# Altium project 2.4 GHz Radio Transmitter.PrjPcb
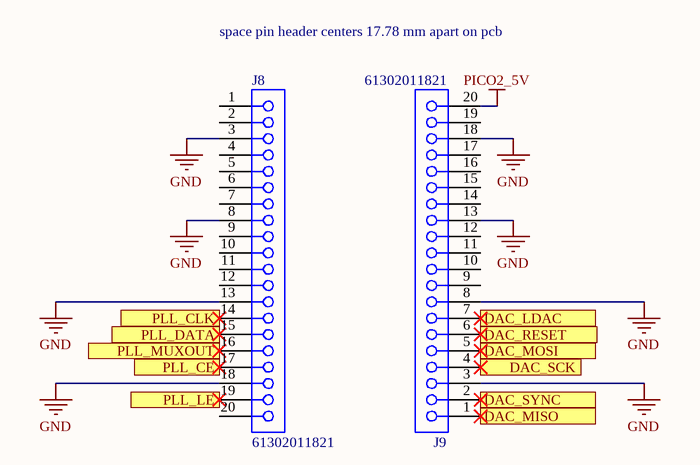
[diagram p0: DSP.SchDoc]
5 sheets, 215 parts. Net scope: flat (ports and power ports of the same name join across sheets).
Board file: 2.4 GHz Radio Transmitter.PcbDoc
Sheets:
  DSP.SchDoc
  PowerFilterLDO.SchDoc
  AnalogBaseband.SchDoc
  FrequencySynthesis.SchDoc
  RF_FrontEnd.SchDoc

## Sheet DSP.SchDoc
size A; SheetNumber: 1; SheetTotal: 5

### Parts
J8  61302011821  [61302011821]
J9  61302011821  [61302011821]

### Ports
DAC_LDAC (see AnalogBaseband[2B]), DAC_MISO (see AnalogBaseband[3A]), DAC_MOSI (see AnalogBaseband[3A]), DAC_RESET (see AnalogBaseband[2B]), DAC_SCK (see AnalogBaseband[3A]), DAC_SYNC (see AnalogBaseband[2A]), PLL_CE (see FrequencySynthesis[3B]), PLL_CLK (see FrequencySynthesis[3B]), PLL_DATA (see FrequencySynthesis[3B]), PLL_LE (see FrequencySynthesis[4B]), PLL_MUXOUT (see FrequencySynthesis[4B])

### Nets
GND: J8.3 J8.8 J8.13 J8.18 J9.3 J9.8 J9.13 J9.18
PICO2_5V: J9.20
NetJ8_14: J8.14 ; port PLL_CLK
NetJ8_15: J8.15 ; port PLL_DATA
NetJ8_16: J8.16 ; port PLL_MUXOUT
NetJ8_17: J8.17 ; port PLL_CE
NetJ8_19: J8.19 ; port PLL_LE
NetJ9_1: J9.1 ; port DAC_MISO
NetJ9_2: J9.2 ; port DAC_SYNC
NetJ9_4: J9.4 ; port DAC_SCK
NetJ9_5: J9.5 ; port DAC_MOSI
NetJ9_6: J9.6 ; port DAC_RESET
NetJ9_7: J9.7 ; port DAC_LDAC

Not connected (* = marked no-connect by the designer): J8 1 2 4 5 6 7 9 10 11 12 20; J9 9 10 11 12 14 15 16 17 19

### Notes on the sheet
- space pin header centers 17.78 mm apart on pcb

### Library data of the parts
J8 J9 = CMP-1502-01348-4: THT Vertical Socket Header WR-PHD, Pitch 2.54 mm, Single Row, 20 pins; Contact Resistance: 20mΩ; Gender: Female; Current Rating: 3A; Operating Supply Voltage: 250V

## Sheet PowerFilterLDO.SchDoc
size B; SheetNumber: 2; SheetTotal: 5
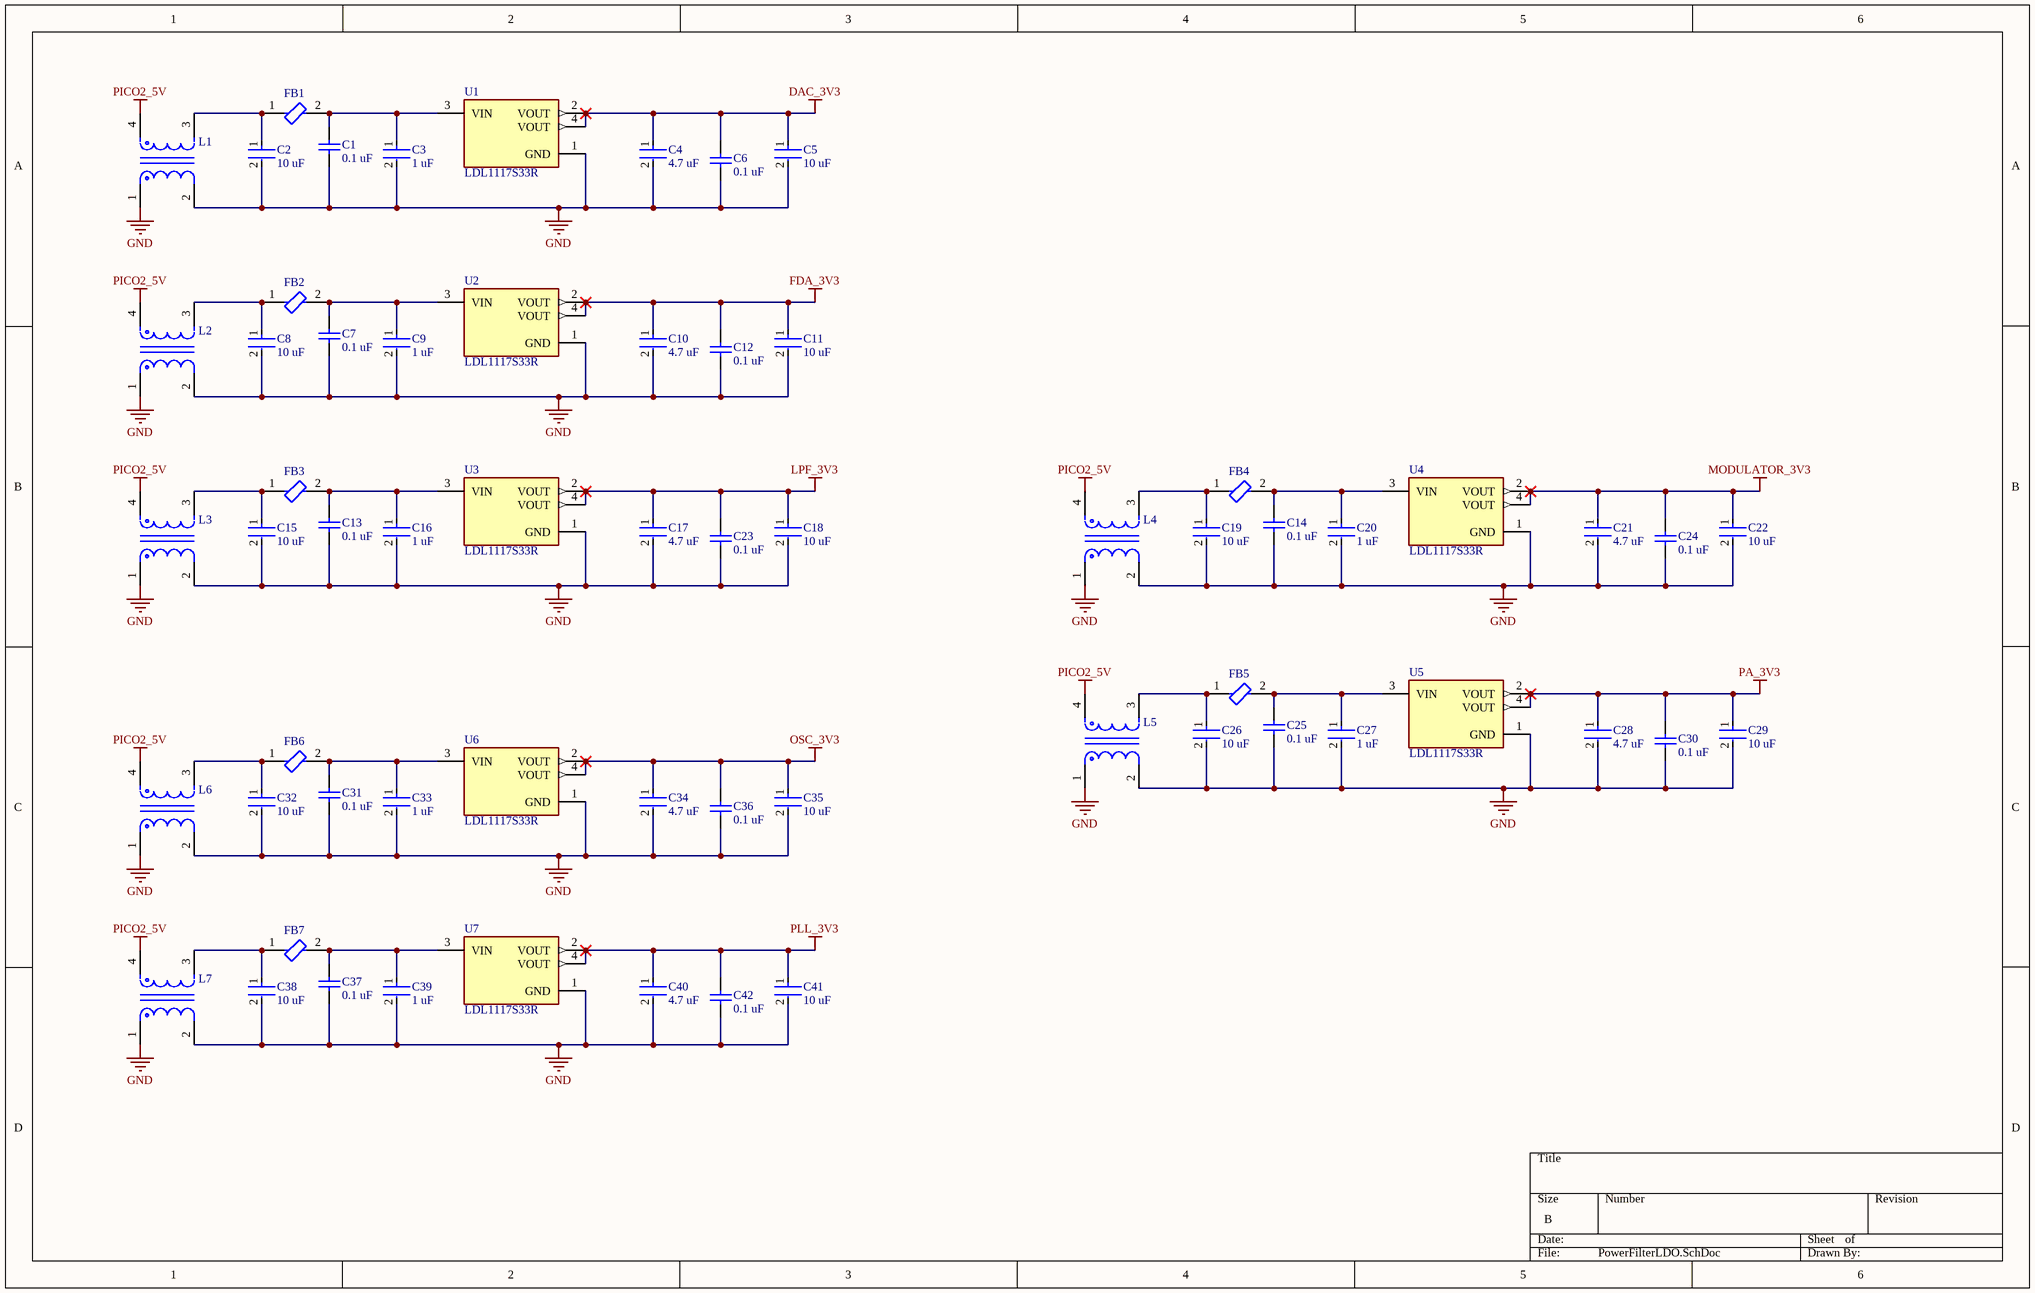
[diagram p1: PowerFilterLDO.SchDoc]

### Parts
C1  0.1 uF  [CAPC1608X95X40LL15T15]
C2  10 uF  [FP-GCM21B-0_15-IPC_A]
C3  1 uF  [FP-VJ0603Y105KXJCW1BC-MFG]
C4  4.7 uF  [FP-GCJ21B-0_3-IPC_A]
C5  10 uF  [FP-GCM21B-0_15-IPC_A]
C6  0.1 uF  [CAPC1608X95X40LL15T15]
C7  0.1 uF  [CAPC1608X95X40LL15T15]
C8  10 uF  [FP-GCM21B-0_15-IPC_A]
C9  1 uF  [FP-VJ0603Y105KXJCW1BC-MFG]
C10  4.7 uF  [FP-GCJ21B-0_3-IPC_A]
C11  10 uF  [FP-GCM21B-0_15-IPC_A]
C12  0.1 uF  [CAPC1608X95X40LL15T15]
C13  0.1 uF  [CAPC1608X95X40LL15T15]
C14  0.1 uF  [CAPC1608X95X40LL15T15]
C15  10 uF  [FP-GCM21B-0_15-IPC_A]
C16  1 uF  [FP-VJ0603Y105KXJCW1BC-MFG]
C17  4.7 uF  [FP-GCJ21B-0_3-IPC_A]
C18  10 uF  [FP-GCM21B-0_15-IPC_A]
C19  10 uF  [FP-GCM21B-0_15-IPC_A]
C20  1 uF  [FP-VJ0603Y105KXJCW1BC-MFG]
C21  4.7 uF  [FP-GCJ21B-0_3-IPC_A]
C22  10 uF  [FP-GCM21B-0_15-IPC_A]
C23  0.1 uF  [CAPC1608X95X40LL15T15]
C24  0.1 uF  [CAPC1608X95X40LL15T15]
C25  0.1 uF  [CAPC1608X95X40LL15T15]
C26  10 uF  [FP-GCM21B-0_15-IPC_A]
C27  1 uF  [FP-VJ0603Y105KXJCW1BC-MFG]
C28  4.7 uF  [FP-GCJ21B-0_3-IPC_A]
C29  10 uF  [FP-GCM21B-0_15-IPC_A]
C30  0.1 uF  [CAPC1608X95X40LL15T15]
C31  0.1 uF  [CAPC1608X95X40LL15T15]
C32  10 uF  [FP-GCM21B-0_15-IPC_A]
C33  1 uF  [FP-VJ0603Y105KXJCW1BC-MFG]
C34  4.7 uF  [FP-GCJ21B-0_3-IPC_A]
C35  10 uF  [FP-GCM21B-0_15-IPC_A]
C36  0.1 uF  [CAPC1608X95X40LL15T15]
C37  0.1 uF  [CAPC1608X95X40LL15T15]
C38  10 uF  [FP-GCM21B-0_15-IPC_A]
C39  1 uF  [FP-VJ0603Y105KXJCW1BC-MFG]
C40  4.7 uF  [FP-GCJ21B-0_3-IPC_A]
C41  10 uF  [FP-GCM21B-0_15-IPC_A]
C42  0.1 uF  [CAPC1608X95X40LL15T15]
FB1  (no value)  [FP-BLM18-0_15-t0_8-IPC_B]
FB2  (no value)  [FP-BLM18-0_15-t0_8-IPC_B]
FB3  (no value)  [FP-BLM18-0_15-t0_8-IPC_B]
FB4  (no value)  [FP-BLM18-0_15-t0_8-IPC_B]
FB5  (no value)  [FP-BLM18-0_15-t0_8-IPC_B]
FB6  (no value)  [FP-BLM18-0_15-t0_8-IPC_B]
FB7  (no value)  [FP-BLM18-0_15-t0_8-IPC_B]
L1  (no value)  [FP-DLW5BS-MFG]
L2  (no value)  [FP-DLW5BS-MFG]
L3  (no value)  [FP-DLW5BS-MFG]
L4  (no value)  [FP-DLW5BS-MFG]
L5  (no value)  [FP-DLW5BS-MFG]
L6  (no value)  [FP-DLW5BS-MFG]
L7  (no value)  [FP-DLW5BS-MFG]
U1  LDL1117S33R  [FP-SOT223-0046067-IPC_A]
U2  LDL1117S33R  [FP-SOT223-0046067-IPC_A]
U3  LDL1117S33R  [FP-SOT223-0046067-IPC_A]
U4  LDL1117S33R  [FP-SOT223-0046067-IPC_A]
U5  LDL1117S33R  [FP-SOT223-0046067-IPC_A]
U6  LDL1117S33R  [FP-SOT223-0046067-IPC_A]
U7  LDL1117S33R  [FP-SOT223-0046067-IPC_A]

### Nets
DAC_3V3: C4.1 C5.1 C6.2 U1.2(VOUT) U1.4(VOUT)
FDA_3V3: C10.1 C11.1 C12.2 U2.2(VOUT) U2.4(VOUT)
GND: C1.1 C2.2 C3.2 C4.2 C5.2 C6.1 C7.1 C8.2 C9.2 C10.2 C11.2 C12.1 C13.1 C14.1 C15.2 C16.2 C17.2 C18.2 C19.2 C20.2 C21.2 C22.2 C23.1 C24.1 C25.1 C26.2 C27.2 C28.2 C29.2 C30.1 C31.1 C32.2 C33.2 C34.2 C35.2 C36.1 C37.1 C38.2 C39.2 C40.2 C41.2 C42.1 L1.1 L1.2 L2.1 L2.2 L3.1 L3.2 L4.1 L4.2 L5.1 L5.2 L6.1 L6.2 L7.1 L7.2 U1.1(GND) U2.1(GND) U3.1(GND) U4.1(GND) U5.1(GND) U6.1(GND) U7.1(GND)
LPF_3V3: C17.1 C18.1 C23.2 U3.2(VOUT) U3.4(VOUT)
MODULATOR_3V3: C21.1 C22.1 C24.2 U4.2(VOUT) U4.4(VOUT)
OSC_3V3: C34.1 C35.1 C36.2 U6.2(VOUT) U6.4(VOUT)
PA_3V3: C28.1 C29.1 C30.2 U5.2(VOUT) U5.4(VOUT)
PICO2_5V: L1.4 L2.4 L3.4 L4.4 L5.4 L6.4 L7.4
PLL_3V3: C40.1 C41.1 C42.2 U7.2(VOUT) U7.4(VOUT)
NetC1_2: C1.2 C3.1 FB1.2 U1.3(VIN)
NetC2_1: C2.1 FB1.1 L1.3
NetC7_2: C7.2 C9.1 FB2.2 U2.3(VIN)
NetC8_1: C8.1 FB2.1 L2.3
NetC13_2: C13.2 C16.1 FB3.2 U3.3(VIN)
NetC14_2: C14.2 C20.1 FB4.2 U4.3(VIN)
NetC15_1: C15.1 FB3.1 L3.3
NetC19_1: C19.1 FB4.1 L4.3
NetC25_2: C25.2 C27.1 FB5.2 U5.3(VIN)
NetC26_1: C26.1 FB5.1 L5.3
NetC31_2: C31.2 C33.1 FB6.2 U6.3(VIN)
NetC32_1: C32.1 FB6.1 L6.3
NetC37_2: C37.2 C39.1 FB7.2 U7.3(VIN)
NetC38_1: C38.1 FB7.1 L7.3

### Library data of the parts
C1 C6 C7 C12-C14 C23-C25 C30 C31 C36 C37 C42 = CMP-2006-01631-1: Ceramic Capacitor, Multilayer, Ceramic, 16V, 20% +Tol, 20% -Tol, X7R, 15% TC, 0.1uF, Surface Mount, 0603; Part Number: VJ0603Y104MXJPW1BC; Manufacturer: Vitramon
C2 C5 C8 C11 C15 C18 C19 C22 C26 C29 C32 C35 C38 C41 = CMP-00075-1: 0805 10 uF 6.3 V ±10% Tolerance X7R Multilayer Ceramic Chip Capacitor; Manufacturer Lifecycle Status: IN PRODUCTION; Voltage Rating: 6.3V; Value: 10µF
C3 C9 C16 C20 C27 C33 C39 = CMP-00030-45106517-1: VJ0603Y105KXJCW1BC Multilayer Ceramic Capacitor, 1 uF, 16 V, ± 10%, X7R, 0603 [1608 Metric]; Capacitance: 1µF; Voltage Rating: 16V; Dielectric Material: Tantalum
C4 C10 C17 C21 C28 C34 C40 = CMP-06035-051513-1: Multilayer Ceramic Capacitors MLCC - SMD/SMT 0805 4.7uF 10%, 16VDC,  X7R 15%; Voltage Rating (DC): 16V
FB1-FB7 = CMP-06046-002207-1: Chip Ferrite Bead, 0603, 180Ω @ 100MHz, 0.09Ω, 25%, 1.5A
L1-L7 = CMP-00050-1: Common Mode Chokes Dual 500Ohm 100MHz 1A 0.23Ohm DCR SMD T/R; Tolerance: 40%; Core Material: Ferrite; Value: 500Ω; Impedance: 2.8kΩ; DC Resistance (DCR): 230mΩ; Insulation Resistance: 10MΩ; Number of Circuits: 2; Voltage Rating: 50V
U1-U7 = CMP-00032-1: LDL1117 Series 1.2 A 3.3 V High PSRR LDO Linear Voltage Regulator-SOT-223

## Sheet AnalogBaseband.SchDoc
size C; SheetNumber: 3; SheetTotal: 5
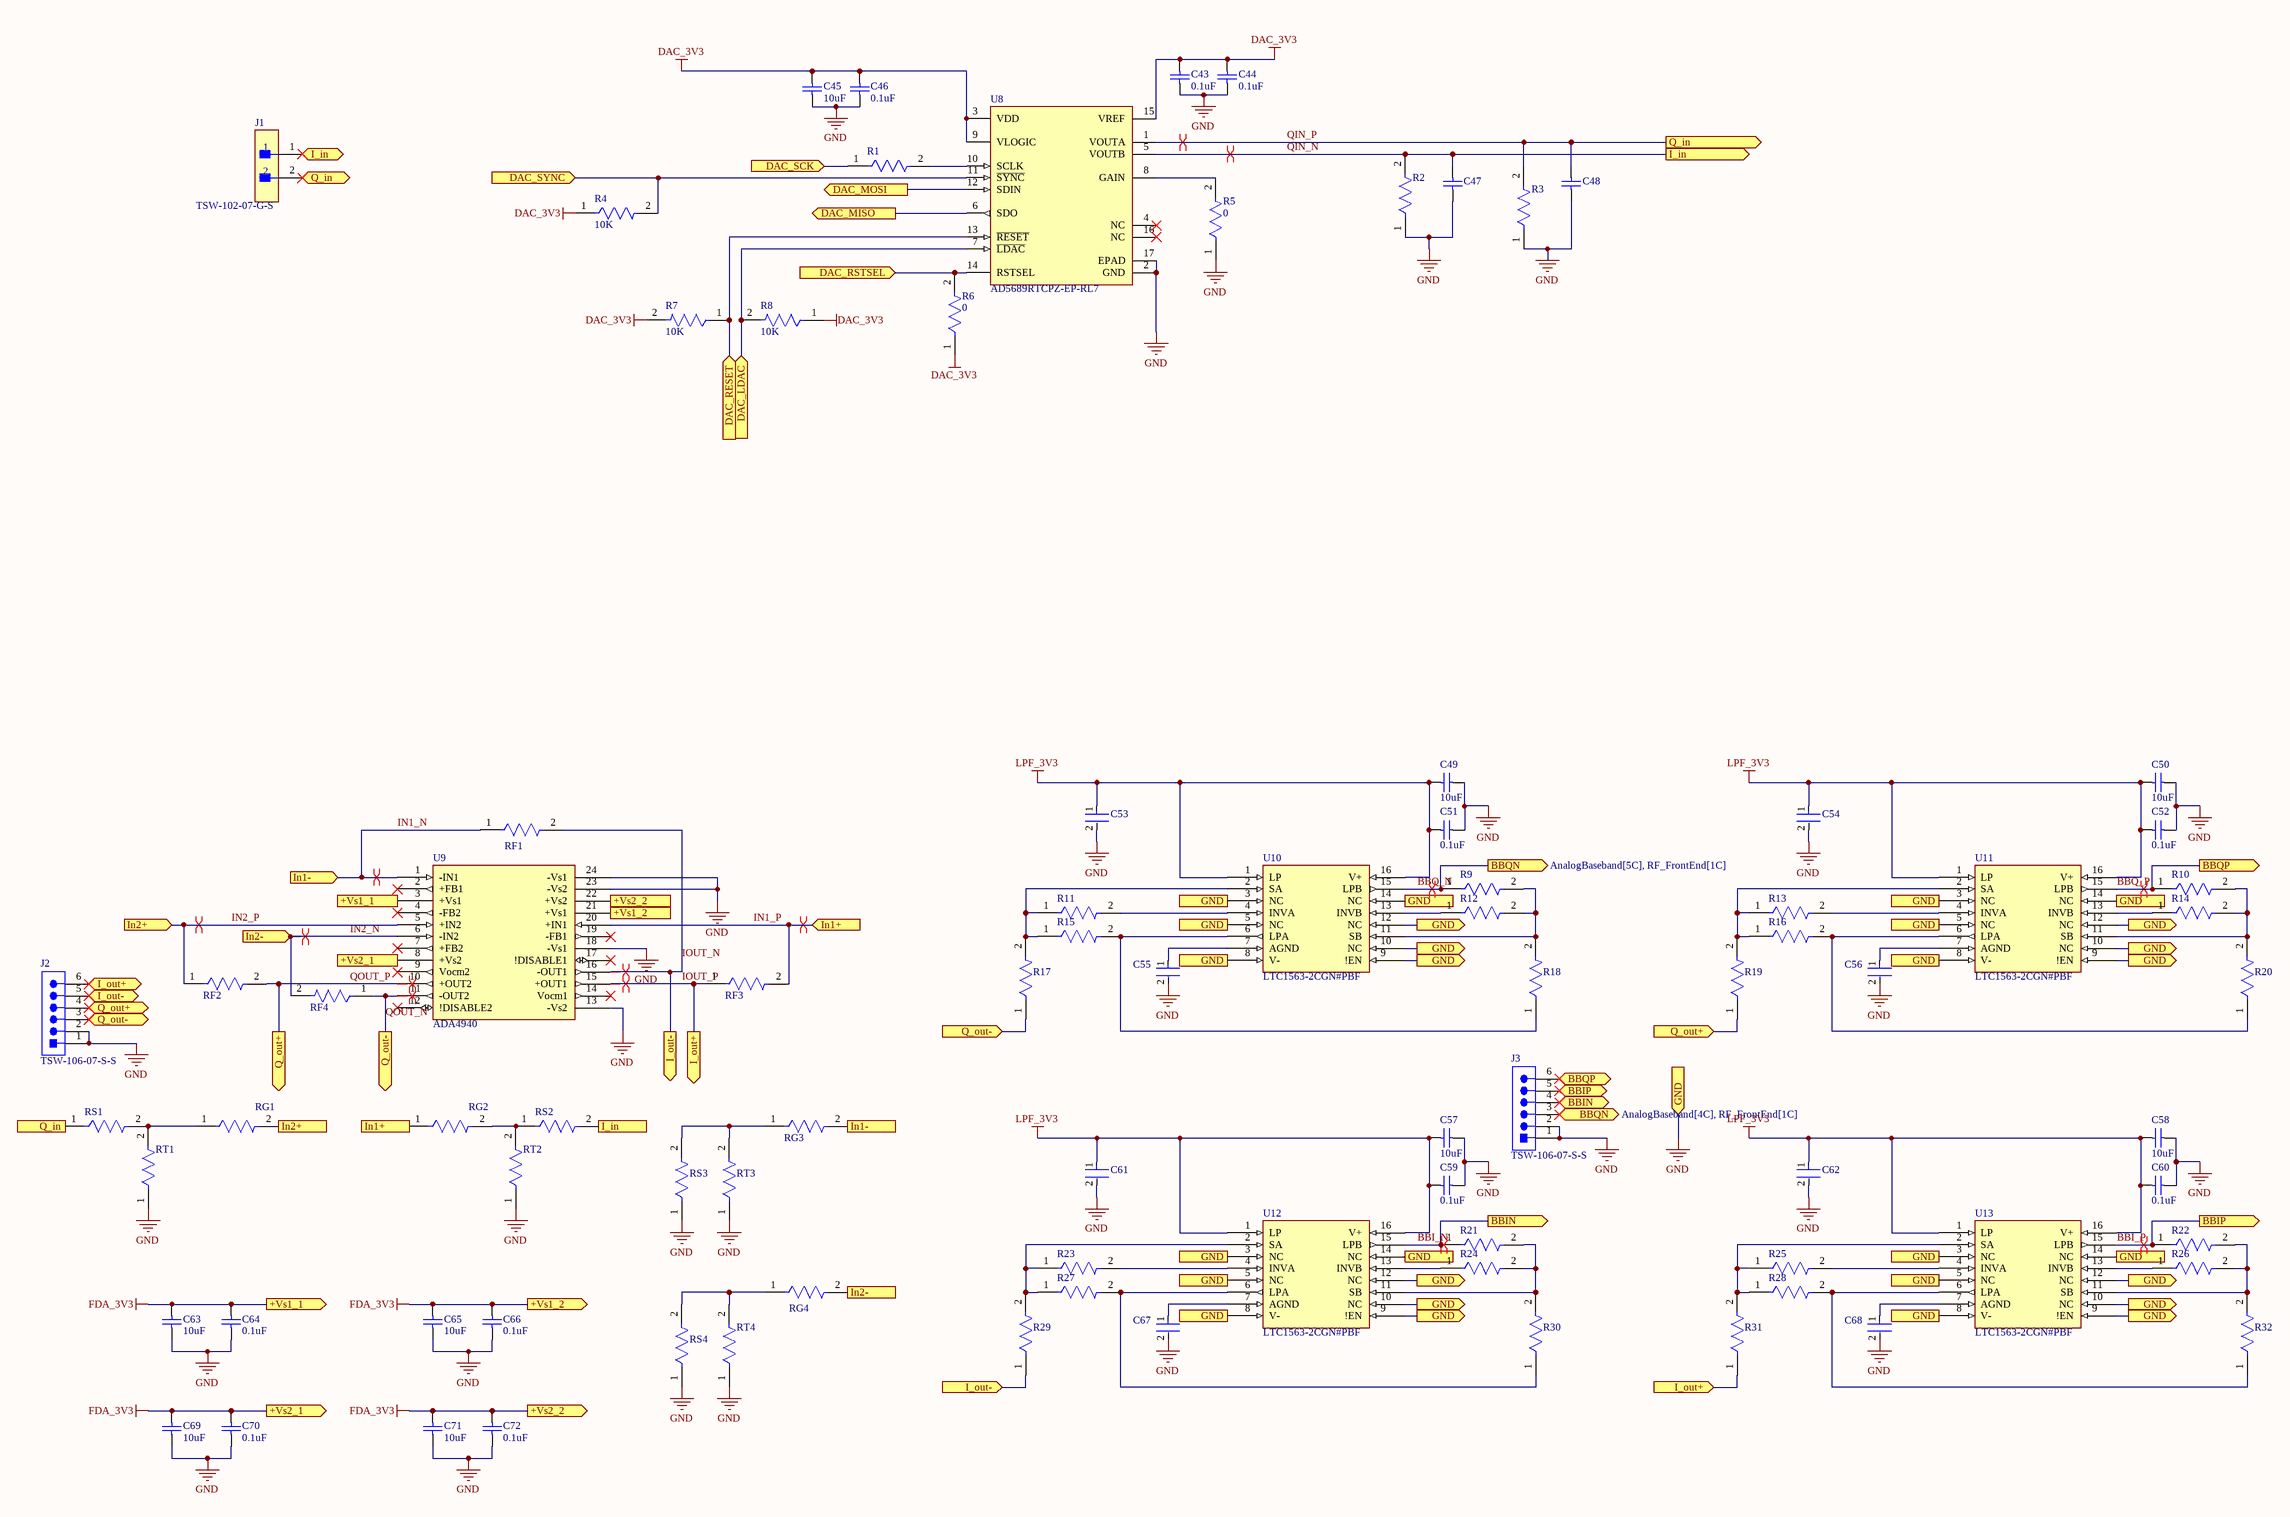
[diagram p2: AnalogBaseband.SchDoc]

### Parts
C43  0.1uF  [CAPC1608X87X35LL15T15]
C44  0.1uF  [CAPC1608X87X35LL15T15]
C45  10uF  [CAPC0603(1608)100_M]
C46  0.1uF  [CAPC1608X87X35LL15T15]
C47  (no value)  [CAPC1608X90X35LL15T15]
C48  (no value)  [CAPC1608X90X35LL15T15]
C49  10uF  [CAPC0603(1608)100_M]
C50  10uF  [CAPC0603(1608)100_M]
C51  0.1uF  [CAPC1608X87X35LL15T15]
C52  0.1uF  [CAPC1608X87X35LL15T15]
C53  CGA5L2C0G1H104J160AA  [FP-CGA5L-MFG]  (value not drawn)
C54  CGA5L2C0G1H104J160AA  [FP-CGA5L-MFG]  (value not drawn)
C55  CGA5L2C0G1H104J160AA  [FP-CGA5L-MFG]  (value not drawn)
C56  CGA5L2C0G1H104J160AA  [FP-CGA5L-MFG]  (value not drawn)
C57  10uF  [CAPC0603(1608)100_M]
C58  10uF  [CAPC0603(1608)100_M]
C59  0.1uF  [CAPC1608X87X35LL15T15]
C60  0.1uF  [CAPC1608X87X35LL15T15]
C61  CGA5L2C0G1H104J160AA  [FP-CGA5L-MFG]  (value not drawn)
C62  CGA5L2C0G1H104J160AA  [FP-CGA5L-MFG]  (value not drawn)
C63  10uF  [CAPC0603(1608)100_M]
C64  0.1uF  [CAPC1608X87X35LL15T15]
C65  10uF  [CAPC0603(1608)100_M]
C66  0.1uF  [CAPC1608X87X35LL15T15]
C67  CGA5L2C0G1H104J160AA  [FP-CGA5L-MFG]  (value not drawn)
C68  CGA5L2C0G1H104J160AA  [FP-CGA5L-MFG]  (value not drawn)
C69  10uF  [CAPC0603(1608)100_M]
C70  0.1uF  [CAPC1608X87X35LL15T15]
C71  10uF  [CAPC0603(1608)100_M]
C72  0.1uF  [CAPC1608X87X35LL15T15]
J1  TSW-102-07-G-S  [FP-TSW-102-07-G-S-MFG]
J2  TSW-106-07-S-S  [SMTC-TSW-106-07-S-S_V]
J3  TSW-106-07-S-S  [SMTC-TSW-106-07-S-S_V]
R1  CRGCQ0603F22R  [FP-CRGCQ0603-IPC_A]  (value not drawn)
R2  (no value)  [FP-CR0603-IPC_B]
R3  (no value)  [FP-CR0603-IPC_B]
R4  10K  [FP-CRGCQ0603-IPC_C]
R5  0  [FP-RMCF0603-IPC_B]
R6  0  [FP-RMCF0603-IPC_B]
R7  10K  [FP-CRGCQ0603-IPC_C]
R8  10K  [FP-CRGCQ0603-IPC_C]
R9  CPF0603B120KE1  [FP-CPF0603-MFG]  (value not drawn)
R10  CPF0603B120KE1  [FP-CPF0603-MFG]  (value not drawn)
R11  CPF0603B120KE1  [FP-CPF0603-MFG]  (value not drawn)
R12  CPF0603B120KE1  [FP-CPF0603-MFG]  (value not drawn)
R13  CPF0603B120KE1  [FP-CPF0603-MFG]  (value not drawn)
R14  CPF0603B120KE1  [FP-CPF0603-MFG]  (value not drawn)
R15  CPF0603B120KE1  [FP-CPF0603-MFG]  (value not drawn)
R16  CPF0603B120KE1  [FP-CPF0603-MFG]  (value not drawn)
R17  CPF0603B120KE1  [FP-CPF0603-MFG]  (value not drawn)
R18  CPF0603B120KE1  [FP-CPF0603-MFG]  (value not drawn)
R19  CPF0603B120KE1  [FP-CPF0603-MFG]  (value not drawn)
R20  CPF0603B120KE1  [FP-CPF0603-MFG]  (value not drawn)
R21  CPF0603B120KE1  [FP-CPF0603-MFG]  (value not drawn)
R22  CPF0603B120KE1  [FP-CPF0603-MFG]  (value not drawn)
R23  CPF0603B120KE1  [FP-CPF0603-MFG]  (value not drawn)
R24  CPF0603B120KE1  [FP-CPF0603-MFG]  (value not drawn)
R25  CPF0603B120KE1  [FP-CPF0603-MFG]  (value not drawn)
R26  CPF0603B120KE1  [FP-CPF0603-MFG]  (value not drawn)
R27  CPF0603B120KE1  [FP-CPF0603-MFG]  (value not drawn)
R28  CPF0603B120KE1  [FP-CPF0603-MFG]  (value not drawn)
R29  CPF0603B120KE1  [FP-CPF0603-MFG]  (value not drawn)
R30  CPF0603B120KE1  [FP-CPF0603-MFG]  (value not drawn)
R31  CPF0603B120KE1  [FP-CPF0603-MFG]  (value not drawn)
R32  CPF0603B120KE1  [FP-CPF0603-MFG]  (value not drawn)
RF1  6-1879336-2  [FP-CPF0603-MFG]  (value not drawn)
RF2  6-1879336-2  [FP-CPF0603-MFG]  (value not drawn)
RF3  6-1879336-2  [FP-CPF0603-MFG]  (value not drawn)
RF4  6-1879336-2  [FP-CPF0603-MFG]  (value not drawn)
RG1  6-1879336-2  [FP-CPF0603-MFG]  (value not drawn)
RG2  6-1879336-2  [FP-CPF0603-MFG]  (value not drawn)
RG3  6-1879336-2  [FP-CPF0603-MFG]  (value not drawn)
RG4  6-1879336-2  [FP-CPF0603-MFG]  (value not drawn)
RS1  CRCW060350R0FKEA  [FP-CRCW0603-e3-IPC_C]  (value not drawn)
RS2  CRCW060350R0FKEA  [FP-CRCW0603-e3-IPC_C]  (value not drawn)
RS3  CRCW060350R0FKEA  [FP-CRCW0603-e3-IPC_C]  (value not drawn)
RS4  CRCW060350R0FKEA  [FP-CRCW0603-e3-IPC_C]  (value not drawn)
RT1  CR0603-FX-52R3ELF  [FP-CR0603-IPC_A]  (value not drawn)
RT2  CR0603-FX-52R3ELF  [FP-CR0603-IPC_A]  (value not drawn)
RT3  CR0603-FX-52R3ELF  [FP-CR0603-IPC_A]  (value not drawn)
RT4  CR0603-FX-52R3ELF  [FP-CR0603-IPC_A]  (value not drawn)
U8  AD5689RTCPZ-EP-RL7  [FP-CP-16-22-IPC_C]
U9  ADA4940  [ADA4940-Footprint-1]
U10  LTC1563-2CGN#PBF  [LTC1563-2CGN#PBF-Footprint-1]
U11  LTC1563-2CGN#PBF  [LTC1563-2CGN#PBF-Footprint-1]
U12  LTC1563-2CGN#PBF  [LTC1563-2CGN#PBF-Footprint-1]
U13  LTC1563-2CGN#PBF  [LTC1563-2CGN#PBF-Footprint-1]

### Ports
+Vs1_1 (in, see AnalogBaseband[1D]), +Vs1_1 (out, see AnalogBaseband[1C]), +Vs1_2 (in, see AnalogBaseband[2D]), +Vs1_2 (out, see AnalogBaseband[2C]), +Vs2_1 (in, see AnalogBaseband[1D]), +Vs2_1 (out, see AnalogBaseband[1C]), +Vs2_2 (in, see AnalogBaseband[2D]), +Vs2_2 (out, see AnalogBaseband[2C]), BBIN (bidir, see AnalogBaseband[4C], RF_FrontEnd[1A]), BBIN (out, see AnalogBaseband[5C], RF_FrontEnd[1A]), BBIP (bidir, see AnalogBaseband[6C], RF_FrontEnd[1A]), BBIP (out, see AnalogBaseband[5C], RF_FrontEnd[1A]), BBQN (bidir, see AnalogBaseband[4C], RF_FrontEnd[1C]), BBQN (out, see AnalogBaseband[5C], RF_FrontEnd[1C]), BBQP (bidir, see AnalogBaseband[6C], RF_FrontEnd[1C]), BBQP (out, see AnalogBaseband[5C], RF_FrontEnd[1C]), DAC_LDAC (in, see DSP[2B]), DAC_MISO (out, see DSP[2C]), DAC_MOSI (out, see DSP[2B]), DAC_RESET (in, see DSP[2B]), DAC_RSTSEL (in), DAC_SCK (in, see DSP[2C]), DAC_SYNC (in, see DSP[2C]), GND (in, see AnalogBaseband[4C], AnalogBaseband[4D], AnalogBaseband[5C], AnalogBaseband[5D], AnalogBaseband[6C], AnalogBaseband[6D]), GND (out, see AnalogBaseband[4C], AnalogBaseband[4D], AnalogBaseband[5C], AnalogBaseband[5D], AnalogBaseband[6C], AnalogBaseband[6D]), I_in (bidir, see AnalogBaseband[2C], AnalogBaseband[5A]), I_in (in, see AnalogBaseband[1A], AnalogBaseband[5A]), I_in (out, see AnalogBaseband[1A], AnalogBaseband[2C]), I_out+ (bidir, see AnalogBaseband[2C], AnalogBaseband[5D]), I_out+ (in, see AnalogBaseband[1C], AnalogBaseband[2C]), I_out+ (out, see AnalogBaseband[1C], AnalogBaseband[5D]), I_out- (bidir, see AnalogBaseband[2C], AnalogBaseband[3D]), I_out- (in, see AnalogBaseband[1C], AnalogBaseband[2C]), I_out- (out, see AnalogBaseband[1C], AnalogBaseband[3D]), In1+ (in, see AnalogBaseband[2C]), In1+ (out, see AnalogBaseband[3C]), In1- (in, see AnalogBaseband[3C]), In1- (out, see AnalogBaseband[1C]), In2+ (in, see AnalogBaseband[1C]), In2+ (out, see AnalogBaseband[1C]), In2- (in, see AnalogBaseband[3D]), In2- (out, see AnalogBaseband[1C]), Q_in (bidir, see AnalogBaseband[1C], AnalogBaseband[5A]), Q_in (in, see AnalogBaseband[1A], AnalogBaseband[5A]), Q_in (out, see AnalogBaseband[1A], AnalogBaseband[1C]), Q_out+ (bidir, see AnalogBaseband[1C], AnalogBaseband[5C]), Q_out+ (in, see AnalogBaseband[1C]), Q_out+ (out, see AnalogBaseband[1C], AnalogBaseband[5C]), Q_out- (bidir, see AnalogBaseband[2C], AnalogBaseband[3C]), Q_out- (in, see AnalogBaseband[1C], AnalogBaseband[2C]), Q_out- (out, see AnalogBaseband[1C], AnalogBaseband[3C])

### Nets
DAC_3V3: C43.2 C44.2 C45.2 C46.2 R4.1 R6.1 R7.2 R8.1 U8.3(VDD) U8.9(VLOGIC) U8.15(VREF)
FDA_3V3: C63.2 C64.2 C65.2 C66.2 C69.2 C70.2 C71.2 C72.2 U9.3(+Vs1) U9.8(+Vs2) U9.21(+Vs1) U9.22(+Vs2) ; port +Vs1_1, port +Vs2_1, port +Vs1_2, port +Vs2_2
GND: C43.1 C44.1 C45.1 C46.1 C47.1 C48.1 C49.1 C50.1 C51.1 C52.1 C53.2 C54.2 C55.2 C56.2 C57.1 C58.1 C59.1 C60.1 C61.2 C62.2 C63.1 C64.1 C65.1 C66.1 C67.2 C68.2 C69.1 C70.1 C71.1 C72.1 J2.1 J2.2 J3.1 J3.2 R2.1 R3.1 R5.1 RS3.1 RS4.1 RT1.1 RT2.1 RT3.1 RT4.1 U8.2(GND) U8.17(EPAD) U9.13(-Vs2) U9.18(-Vs1) U9.23(-Vs2) U9.24(-Vs1) U10.3(NC) U10.5(NC) U10.8(V-) U10.9(!EN) U10.10(NC) U10.12(NC) U10.14(NC) U11.3(NC) U11.5(NC) U11.8(V-) U11.9(!EN) U11.10(NC) U11.12(NC) U11.14(NC) U12.3(NC) U12.5(NC) U12.8(V-) U12.9(!EN) U12.10(NC) U12.12(NC) U12.14(NC) U13.3(NC) U13.5(NC) U13.8(V-) U13.9(!EN) U13.10(NC) U13.12(NC) U13.14(NC) ; port GND
LPF_3V3: C49.2 C50.2 C51.2 C52.2 C53.1 C54.1 C57.2 C58.2 C59.2 C60.2 C61.1 C62.1 U10.1(LP) U10.16(V+) U11.1(LP) U11.16(V+) U12.1(LP) U12.16(V+) U13.1(LP) U13.16(V+)
BBI_N: J3.4 R21.1 U12.15(LPB) ; port BBIN
BBI_P: J3.5 R22.1 U13.15(LPB) ; port BBIP
BBQ_N: J3.3 R9.1 U10.15(LPB) ; port BBQN
BBQ_P: J3.6 R10.1 U11.15(LPB) ; port BBQP
IN1_N: RF1.1 RG3.2 U9.1(-IN1) ; port In1-
IN1_P: RF3.2 RG2.1 U9.20(+IN1) ; port In1+
IN2_N: RF4.2 RG4.2 U9.6(-IN2) ; port In2-
IN2_P: RF2.1 RG1.2 U9.5(+IN2) ; port In2+
IOUT_N: J2.5 R29.1 RF1.2 U9.16(-OUT1) ; port I_out-
IOUT_P: J2.6 R31.1 RF3.1 U9.15(+OUT1) ; port I_out+
QIN_N: C47.2 J1.1 R2.2 RS2.2 U8.5(VOUTB) ; port I_in
QIN_P: C48.2 J1.2 R3.2 RS1.1 U8.1(VOUTA) ; port Q_in
QOUT_N: J2.3 R17.1 RF4.1 U9.11(-OUT2) ; port Q_out-
QOUT_P: J2.4 R19.1 RF2.2 U9.10(+OUT2) ; port Q_out+
NetC55_1: C55.1 U10.7(AGND)
NetC56_1: C56.1 U11.7(AGND)
NetC67_1: C67.1 U12.7(AGND)
NetC68_1: C68.1 U13.7(AGND)
NetJ9_1: U8.6(SDO) ; port DAC_MISO
NetJ9_2: R4.2 U8.11(~{SYNC}) ; port DAC_SYNC
NetJ9_4: R1.1 ; port DAC_SCK
NetJ9_5: U8.12(SDIN) ; port DAC_MOSI
NetJ9_6: R7.1 U8.13(~{RESET}) ; port DAC_RESET
NetJ9_7: R8.2 U8.7(~{LDAC}) ; port DAC_LDAC
NetR1_2: R1.2 U8.10(SCLK)
NetR5_2: R5.2 U8.8(GAIN)
NetR6_2: R6.2 U8.14(RSTSEL) ; port DAC_RSTSEL
NetR9_2: R9.2 R12.2 R18.2 U10.11(SB)
NetR10_2: R10.2 R14.2 R20.2 U11.11(SB)
NetR11_1: R11.1 R15.1 R17.2 U10.2(SA)
NetR11_2: R11.2 U10.4(INVA)
NetR12_1: R12.1 U10.13(INVB)
NetR13_1: R13.1 R16.1 R19.2 U11.2(SA)
NetR13_2: R13.2 U11.4(INVA)
NetR14_1: R14.1 U11.13(INVB)
NetR15_2: R15.2 R18.1 U10.6(LPA)
NetR16_2: R16.2 R20.1 U11.6(LPA)
NetR21_2: R21.2 R24.2 R30.2 U12.11(SB)
NetR22_2: R22.2 R26.2 R32.2 U13.11(SB)
NetR23_1: R23.1 R27.1 R29.2 U12.2(SA)
NetR23_2: R23.2 U12.4(INVA)
NetR24_1: R24.1 U12.13(INVB)
NetR25_1: R25.1 R28.1 R31.2 U13.2(SA)
NetR25_2: R25.2 U13.4(INVA)
NetR26_1: R26.1 U13.13(INVB)
NetR27_2: R27.2 R30.1 U12.6(LPA)
NetR28_2: R28.2 R32.1 U13.6(LPA)
NetRG1_1: RG1.1 RS1.2 RT1.2
NetRG2_2: RG2.2 RS2.1 RT2.2
NetRG3_1: RG3.1 RS3.2 RT3.2
NetRG4_1: RG4.1 RS4.2 RT4.2

Not connected (* = marked no-connect by the designer): U8 4(NC)* 16(NC)*; U9 2(+FB1)* 4(-FB2)* 7(+FB2)* 9(Vocm2)* 12(!DISABLE2)* 14(Vocm1)* 17(!DISABLE1)* 19(-FB1)*

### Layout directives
differential pair: BBI_N, BBI_P, BBQ_N, BBQ_P, IN1_N, IN1_P, IN2_N, IN2_P, IOUT_N, IOUT_P, QIN_N, QIN_P, QOUT_N, QOUT_P

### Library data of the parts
C43 C44 C46 C51 C52 C59 C60 C64 C66 C70 C72 = CMP-00023-1: Ceramic Capacitor, Multilayer, Ceramic, 25V, 10% +Tol, 10% -Tol, X7R, 15% TC, 0.1uF, Surface Mount, 0603
C45 C49 C50 C57 C58 C63 C65 C69 C71 = CMP-1035-02796-1: CAP 10uF 6.3V ±10% 0603 (1608 Metric) Thickness 1mm SMD; Case-EIA: 0603; Tolerance: Â±10%; Case-Metric: 1608
C47 C48 = CMP-2006-04266-1: 200pF; Manufacturer: AVX Interconnect / Elco; Part Number: 06035A201FAT2A
C53-C56 C61 C62 C67 C68 = CMP-00052-1: CGA Series 1206 100 nF 50 V ±5 % Tolerance C0G SMT Multilayer Ceramic Capacitor
J1 = CMP-02766-000084-1: CONN HEADER VERT 2POS 2.54MM; Manufacturer: Samtec; Number Of Contacts: 2; Voltage Rating: 550V; Conn Orientation: Straight; Current Rating: 6.3A; Conn Gender: Male
J2 J3 = CMP-1681-00007-2: Male Header, Pitch 2.54 mm, 1 x 6 Position, Height 8.38 mm, Tail Length 2.54 mm, -55 to 125 degC, RoHS, Bulk; Manufacturer: Samtec; Rows: 1
R1 = CMP-00035-1: Res Thick Film 0603 22 Ohm 1% 0.1W(1/10W) ±200ppm/C Pad SMD Automotive T/R
R2 R3 = CMP-07231-005094-1: Thick Film Chip Resistors 0603 2kΩ 0.1W 5% 200ppm/°C; Resistance: 2kR; Power Rating: 100mW; Voltage Rating: 50V
R4 R7 R8 = CMP-03211-009884-1: CRGCQ 0603 10K 5%; Manufacturer Part Number: CRGCQ0603J10K; Manufacturer: TE Connectivity; Tolerance: 0.05; Power Rating: 0.1W; Resistance: 10KΩ; Voltage Rating: 75V; Value: 10KΩ; Temperature Coefficient: ±100ppm/°C
R5 R6 = CMP-26527-006412-1: 0Ω ±0 0.1W 0603 Thick Film Chip Resistor AEC-Q200 compliant; Max Power Dissipation: 100mW; Resistance: 0R
R9-R32 = CMP-00034-1: Res Thin Film 0603 120K Ohm 0.1% 1/16W ±25ppm/°C Molded SMD SMD Paper T/R
RF1-RF4 RG1-RG4 = CMP-00029-1: Fixed Resistor, Thin Film, 0.063W, 1000ohm, 50V, 1% +/-Tol, 50ppm/Cel, Surface Mount, 0603
RS1-RS4 = CMP-00028-1: Res Thick Film 0603 50 Ohm 1% 0.1W(1/10W) ±100ppm/C Pad SMD Automotive T/R
RT1-RT4 = CMP-00030-1: Resistor, thick film, SMD 0603 (1608), 52.3 Ω, 0.1 W, ±1 %, CR0603-FX-52R3ELF
U8 = CMP-09082-000052-1: IC DAC 16BIT V-OUT 16LFCSP; Min Output Voltage: 0uV; Number of DAC Channels: 2; Power Dissipation: 7.2mW; Max Supply Voltage: 5.5V; Number of Bits: 16; Resolution: 16b; Interface: SPI; Sampling Rate: 6.3MS/s; Output Type: Voltage; Operating Supply Voltage: 3V; Polarity: Unipolar; Settling Time: 5us; Integral Nonlinearity (INL): 4LSB; Signal to Noise Ratio (SNR): 90dB; Differential Output: No
U9 = CMP-00021-4: ROHS3Compliant EAR99 ADA4940 Tape & Reel (TR) op amp amplifier circuit 3mm 1.1muA 60muV 90dB
U10-U13 = CMP-00022-3: Active Filter Dual Low Pass 8th Order 256kHz 16-Pin SSOP N

## Sheet FrequencySynthesis.SchDoc
size B; SheetNumber: 4; SheetTotal: 5
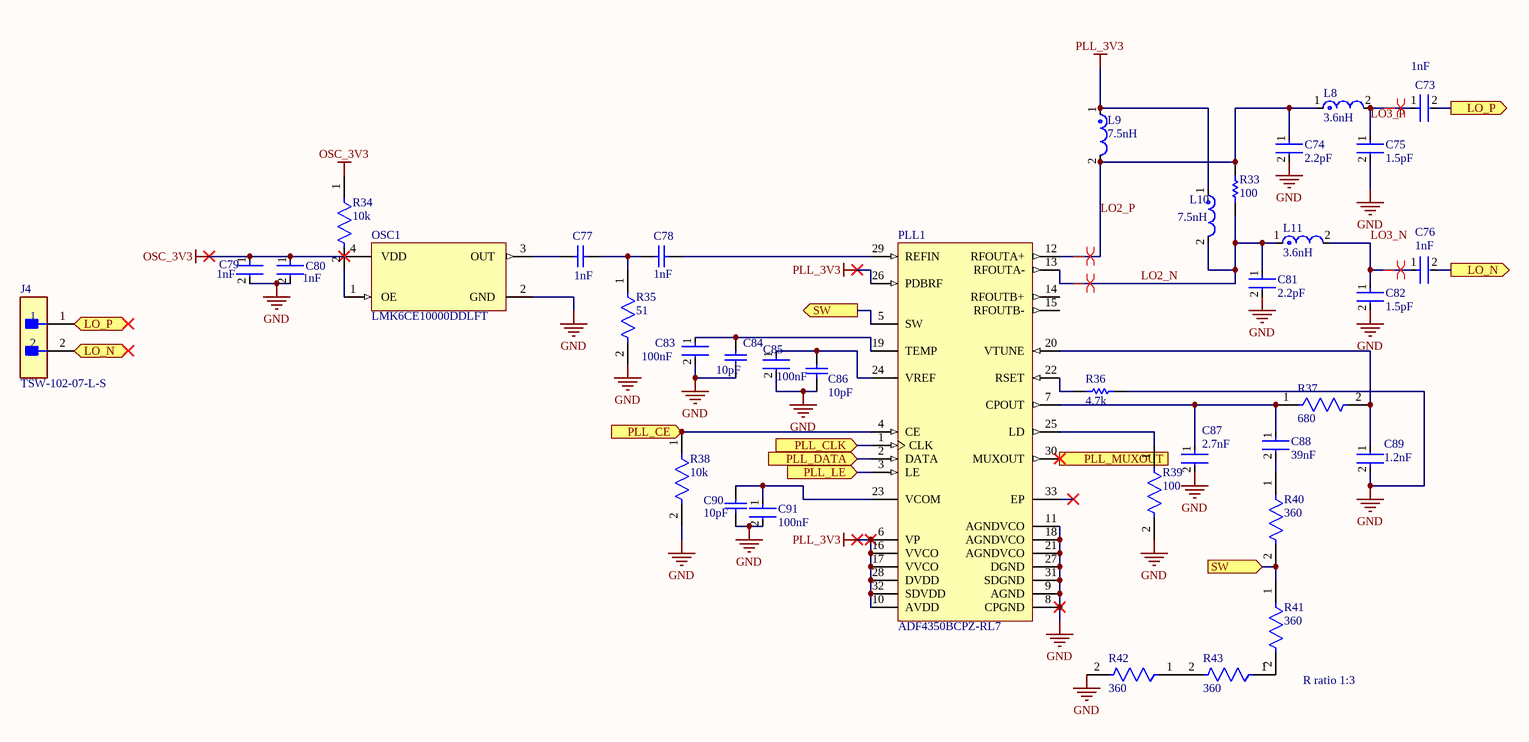
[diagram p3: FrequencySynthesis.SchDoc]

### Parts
C73  1nF  [FP-C0402C102K4RAC7411-MFG]
C74  2.2pF  [FP-CGA2B-IPC_B]
C75  1.5pF  [FP-GCM155-0_05-IPC_A]
C76  1nF  [FP-C0402C102K4RAC7411-MFG]
C77  1nF  [CAPC1608X95X40NL15T15]
C78  1nF  [CAPC1608X95X40NL15T15]
C79  1nF  [FP-CGA3E-0_3-0_1-IPC_A]
C80  1nF  [FP-CGA3E-0_3-0_1-IPC_A]
C81  2.2pF  [FP-CGA2B-IPC_B]
C82  1.5pF  [FP-CGA2B-MFG]
C83  100nF  [FP-GRM31C-0_2-e0_3_0_8-IPC_B]
C84  10pF  [CAPC1608X92X38LL15T08]
C85  100nF  [FP-GRM31C-0_2-e0_3_0_8-IPC_B]
C86  10pF  [CAPC1608X92X38LL15T08]
C87  2.7nF  [FP-C2012-125-0_2-IPC_A]
C88  39nF  [FP-C1206C-EB-MFG]
C89  1.2nF  [FP-C1608-080-0_1-IPC_C]
C90  10pF  [CAPC1608X92X38LL15T08]
C91  100nF  [FP-CGA5L-0_3-0_1-IPC_A]
J4  TSW-102-07-L-S  [FP-TSW-102-07-L-S-MFG]
L8  3.6nH  [FP-LQG15HH_02-MFG]
L9  7.5nH  [FP-LQG15WH_02-MFG]
L10  7.5nH  [FP-LQG15WH_02-MFG]
L11  3.6nH  [FP-LQG15HH_02-MFG]
OSC1  LMK6CE10000DDLFT  [DLF0004A_MFG]
PLL1  ADF4350BCPZ-RL7  [ADI-CP-32-2_L]
R33  100  [RESC1609X50X30LL10T20]
R34  10k  [FP-CRG0402-IPC_B]
R35  51  [FP-CRCW0603-e3-IPC_B]
R36  4.7k  [RESC1609X50X30NL10T20]
R37  680  [FP-RT0402-MFG]
R38  10k  [FP-MCT0603-IPC_B]
R39  100  [FP-SR0603-MFG]
R40  360  [FP-CRCW0402-e3-IPC_C]
R41  360  [FP-CRCW0402-e3-IPC_C]
R42  360  [FP-CRCW0402-e3-IPC_C]
R43  360  [FP-CRCW0402-e3-IPC_C]

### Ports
LO_N (bidir, see FrequencySynthesis[5B], RF_FrontEnd[1B]), LO_N (out, see FrequencySynthesis[1B], RF_FrontEnd[1B]), LO_P (bidir, see FrequencySynthesis[5A], RF_FrontEnd[1B]), LO_P (out, see FrequencySynthesis[1B], RF_FrontEnd[1B]), PLL_CE (in, see DSP[1C]), PLL_CLK (in, see DSP[1B]), PLL_DATA (in, see DSP[1B]), PLL_LE (in, see DSP[1C]), PLL_MUXOUT (out, see DSP[1B]), SW (in, see FrequencySynthesis[4B]), SW (out, see FrequencySynthesis[5C])

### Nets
GND: C74.2 C75.2 C79.2 C80.2 C81.2 C82.2 C83.2 C84.1 C85.2 C86.1 C87.2 C89.2 C90.1 C91.2 OSC1.2(GND) PLL1.8(CPGND) PLL1.9(AGND) PLL1.11(AGNDVCO) PLL1.18(AGNDVCO) PLL1.21(AGNDVCO) PLL1.27(DGND) PLL1.31(SDGND) R35.2 R36.2 R38.2 R39.2 R42.2
OSC_3V3: C79.1 C80.1 OSC1.4(VDD) R34.1
PLL_3V3: L9.1 L10.1 PLL1.6(VP) PLL1.10(AVDD) PLL1.16(VVCO) PLL1.17(VVCO) PLL1.26(PDBRF) PLL1.28(DVDD) PLL1.32(SDVDD)
LO2_N: C81.1 L10.2 L11.1 PLL1.13(RFOUTA-) R33.1
LO2_P: C74.1 L8.1 L9.2 PLL1.12(RFOUTA+) R33.2
LO3_N: C76.1 C82.1 L11.2
LO3_P: C73.1 C75.1 L8.2
LO_N: C76.2 J4.2 ; port LO_N
LO_P: C73.2 J4.1 ; port LO_P
NetC77_1: C77.1 OSC1.3(OUT)
NetC77_2: C77.2 C78.1 R35.1
NetC78_2: C78.2 PLL1.29(REFIN)
NetC83_1: C83.1 C84.2 PLL1.19(TEMP)
NetC85_1: C85.1 C86.2 PLL1.24(VREF)
NetC87_1: C87.1 C88.1 PLL1.7(CPOUT) R37.1
NetC88_2: C88.2 R40.1
NetC89_1: C89.1 PLL1.20(VTUNE) R37.2
NetC90_2: C90.2 C91.1 PLL1.23(VCOM)
NetJ8_14: PLL1.1(CLK) ; port PLL_CLK
NetJ8_15: PLL1.2(DATA) ; port PLL_DATA
NetJ8_16: PLL1.30(MUXOUT) ; port PLL_MUXOUT
NetJ8_17: PLL1.4(CE) R38.1 ; port PLL_CE
NetJ8_19: PLL1.3(LE) ; port PLL_LE
NetOSC1_1: OSC1.1(OE) R34.2
NetPLL1_5: PLL1.5(SW) R40.2 R41.1 ; port SW
NetPLL1_22: PLL1.22(RSET) R36.1
NetPLL1_25: PLL1.25(LD) R39.1
NetR41_2: R41.2 R43.1
NetR42_1: R42.1 R43.2

Not connected (* = marked no-connect by the designer): PLL1 14(RFOUTB+) 15(RFOUTB-) 33(EP)*

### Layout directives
differential pair: LO2_N, LO2_P, LO3_N, LO3_P

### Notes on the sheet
- R ratio 1:3

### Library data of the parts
C73 C76 = CMP-03020-021251-2: CAP CER 1000PF 16V X7R 0402; Dielectric Material: Ceramic; Tolerance: 10%
C74 C81 = CMP-08246-000350-1: Cap Ceramic 2.2pF 50V C0G 0.25pF Pad SMD 0402 +125°C Automotive T/R
C75 = CMP-06035-012333-1: Ceramic Capacitor for Automotive 1.5pF ±5% 50VDC C0G 0402 Paper T/R; Voltage Rating: 50V
C77 C78 = CMP-2006-01663-1: Manufacturer: Vitramon; Part Number: VJ0603A102JXXCW1BC
C79 C80 = CMP-08246-001196-1: Cap Ceramic 1nF 250V C0G 5% Pad SMD 0603 +125°C Automotive T/R
C82 = CMP-08246-001768-1: Cap Ceramic 1.5pF 50V C0G 0.25pF Pad SMD 0402 +125°C Automotive T/R
C83 C85 = CMP-06035-003994-1: Chip Multilayer Ceramic Capacitors for General Purpose, 1206, 0.10uF, C0G, 30ppm/°C, 5%, 50V
C84 C86 C90 = CMP-2006-01151-1: Manufacturer: Vitramon; Part Number: VJ0603A100JXBAC
C87 = CMP-08246-005643-1: Multilayer Ceramic Capacitors 2.7nF ±5% 250V C0G SMD 0805
C88 = CMP-03020-008489-1: C1206 39,000 pF C0G 5.00% 50 V; Manufacturer Part Number: C1206C393J5GACTU; Manufacturer: KEMET; Temperature Coefficient: 15%; Material: Ceramic; Automotive Grade: Grade 0; Voltage Rating: 50 V; Tolerance: 0.05
C89 = CMP-08246-006367-1: Multilayer Ceramic Capacitors 1.2nF ±5% 100V C0G SMD 0603
C91 = CMP-08246-001706-1: Cap Ceramic 100nF 100V C0G 5% Pad SMD 1206 +125°C Automotive T/R
J4 = CMP-02766-001428-1: CONN HEADER VERT 2POS 2.54MM; Voltage Rating: 550V; Current Rating: 7.6A; Gender: Male; Number of Contacts: 2; Connector Type: Male Pin
L8 L11 = CMP-06042-009995-1: Multilayer type RF Inductor 3.6nH ±0.2nH 0.14Ω 750mA 0402; Core Material: Air; Self Resonant Frequency: 6GHz; Shielding: Unshielded; Test Frequency: 100MHz; DC Resistance (DCR): 140mR
L9 L10 = CMP-06042-014192-1: Multilayer type Inductor for Automotive 7.5nH ±3% 0.16Ω 600mA 0402; Shielding: Unshielded; Test Frequency: 100MHz; Core Material: Air; DC Resistance (DCR): 160mR; Self Resonant Frequency: 4GHz
OSC1 = CMP-00370-145325626-1: IC 100 MHz LVCMOS Oscillator 1.8V Enable/Disable 4-VDFN; Manufacturer Lifecycle Status: ACTIVE; Frequency: 100MHz; Load Capacitance: 15pF; Max Supply Current: 44mA; Max Junction Temperature (Tj): 125°C; Max Supply Voltage: 1.9V; Min Supply Voltage: 1.7V
PLL1 = CMP-0287-00013-1: Wideband Synthesizer with Integrated VCO, CP-32-2, Pb-Free, 1500 Reel; RF Prescalers: 4/5, 8/9; Single/Dual: Single; Max RF Input (MHz): 4.4GHz; Supply Current: 110mA; Frequency Range: 137.5MHz-4.35GHz; Max REFin (MHz): 250MHz; Norm Phase Noise (dBc/Hz): -220dBc
R33 = CMP-2000-03826-1: Manufacturer: Vishay Dale; Part Number: CRCW0603100RFKTA
R34 = CMP-03211-011410-1: RES SMD 10K OHM 1% 1/16W 0402; Resistance: 10kR; Voltage Rating (DC): 50V; Temperature Coefficient: 100ppm/°C; Max Power Dissipation: 63mW; Number of Resistors: 1
R35 = CMP-2000-03447-2: RES Thick Film, 51Ω, 5%, 0.1W, 200ppm/°C, 0603; Max Power Dissipation: 100mW; Working Voltage: 75V; Resistance: 51R
R36 = CMP-2000-03412-1: Manufacturer: Vishay Dale; Part Number: CRCW06034K70FKTA
R37 = CMP-2002-02756-2: RES SMD 680 OHM 0.1% 1/16W 0402; Manufacturer: Yageo; Manufacturer Part Number: RT0402BRD07680RL; Resistance: 680Ω; Value: 680Ω; Power Rating: 0.063W; Tolerance: 0.001; Temperature Coefficient: 25 ppm/°C; Voltage Rating: 50V
R38 = CMP-02407-001090-1: RES SMD 100 OHM 1% 1/8W 0603
R39 = CMP-03412-002710-1: RES SMD 0603 1/4W 1% 100 OHM; Manufacturer Part Number: SR0603FR-7T100RL; Manufacturer: Yageo; Power Rating: 0.25W; Voltage Rating: 75V; Automotive Grade: Grade 0; Resistance: 100Ω; Tolerance: 0.01; Value: 100Ω
R40-R43 = CMP-2002-08546-2: RES Thick Film, 360Ω, 1%, 0.063W, 100ppm/°C, 0402; Voltage Rating: 50V; Max Power Dissipation: 63mW; Resistance: 360R

## Sheet RF_FrontEnd.SchDoc
size A; SheetNumber: 5; SheetTotal: 5
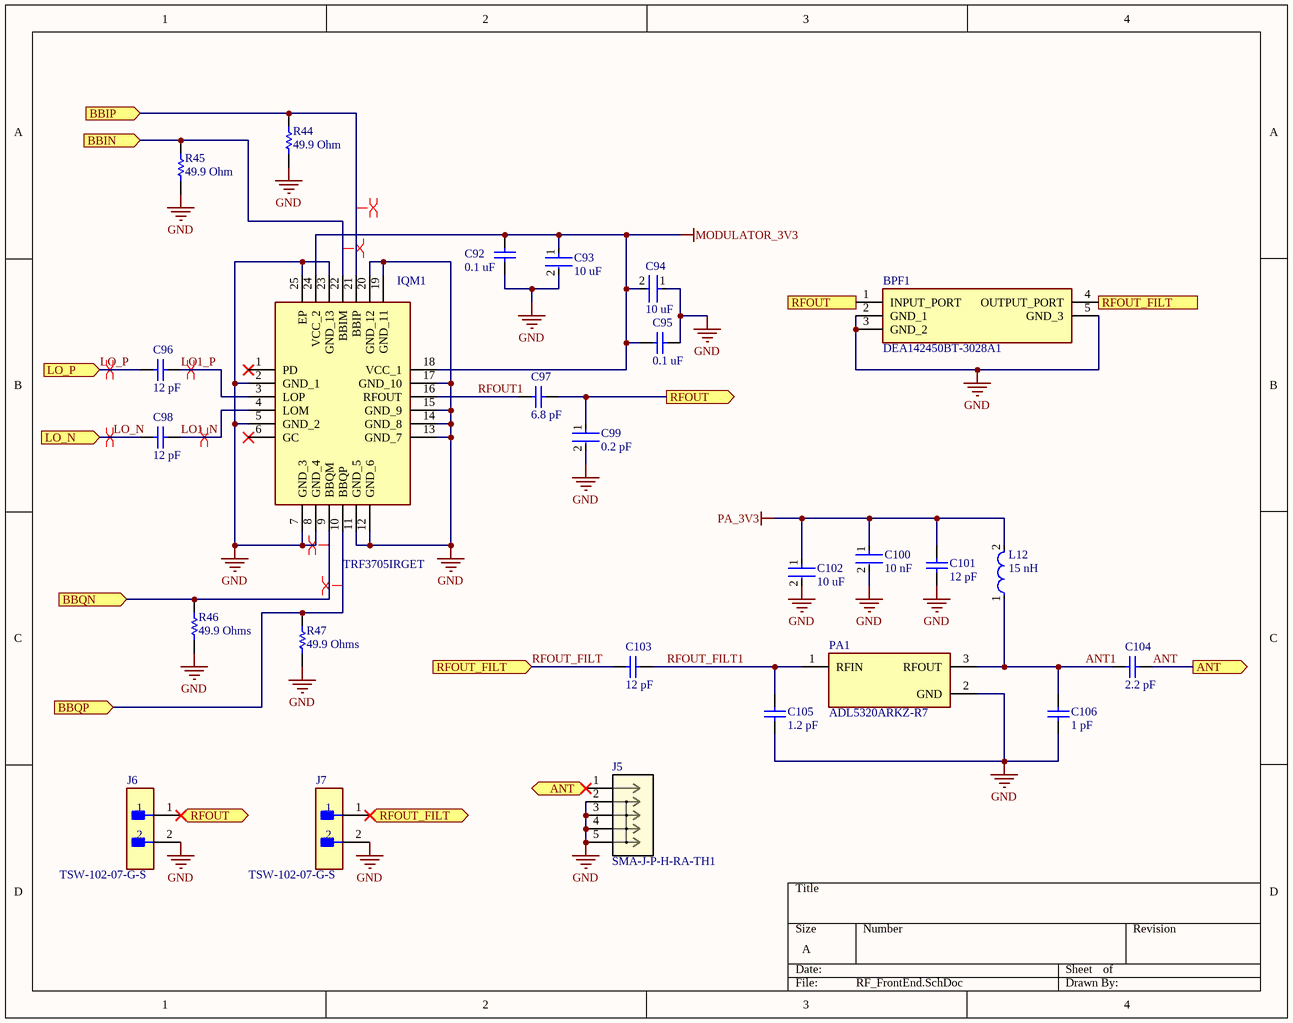
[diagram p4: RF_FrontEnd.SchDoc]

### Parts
BPF1  DEA142450BT-3028A1  [DEA142450BT3028A1]
C92  0.1 uF  [CAPC1608X95X40LL15T15]
C93  10 uF  [FP-GCM21B-0_15-IPC_A]
C94  10 uF  [FP-GCM21B-0_15-IPC_A]
C95  0.1 uF  [CAPC1608X95X40LL15T15]
C96  12 pF  [CAPC1608X95X40ML15T15]
C97  6.8 pF  [CAPC0603(1608)100_L]
C98  12 pF  [CAPC1608X95X40ML15T15]
C99  0.2 pF  [FP-GQM187-0_15-IPC_C]
C100  10 nF  [FP-GRM188-0_1-e0_2_0_5-IPC_B]
C101  12 pF  [CAPC1608X95X40ML15T15]
C102  10 uF  [FP-GCM21B-0_15-IPC_A]
C103  12 pF  [CAPC1608X95X40ML15T15]
C104  2.2 pF  [CAPC0603(1608)100_N]
C105  1.2 pF  [CAPC1608X92X38NL15T08]
C106  1 pF  [CAPC1608X95X40LL15T15]
IQM1  TRF3705IRGET  [QFN50P400X400X100-25N-D]
J5  SMA-J-P-H-RA-TH1  [CONN_SMA-J-P-H-RA-TH1_SAI]
J6  TSW-102-07-G-S  [FP-TSW-102-07-G-S-MFG]
J7  TSW-102-07-G-S  [FP-TSW-102-07-G-S-MFG]
L12  15 nH  [FP-LQW18CA_00-MFG]
PA1  ADL5320ARKZ-R7  [FP-RK-3-MFG]
R44  49.9 Ohm  [RESC1609X55X30NL10T20]
R45  49.9 Ohm  [RESC1609X55X30NL10T20]
R46  49.9 Ohms  [RESC1609X55X30NL10T20]
R47  49.9 Ohms  [RESC1609X55X30NL10T20]

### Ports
ANT (bidir, see RF_FrontEnd[4C]), ANT (out, see RF_FrontEnd[2D]), BBIN (in, see AnalogBaseband[4C], AnalogBaseband[5C]), BBIP (in, see AnalogBaseband[5C], AnalogBaseband[6C]), BBQN (in, see AnalogBaseband[4C]), BBQP (in, see AnalogBaseband[5C], AnalogBaseband[6C]), LO_N (in, see FrequencySynthesis[1B], FrequencySynthesis[5B]), LO_P (in, see FrequencySynthesis[1B], FrequencySynthesis[5A]), RFOUT (bidir, see RF_FrontEnd[3B]), RFOUT (in, see RF_FrontEnd[1D], RF_FrontEnd[3B]), RFOUT (out, see RF_FrontEnd[1D], RF_FrontEnd[3B]), RFOUT_FILT (bidir, see RF_FrontEnd[2C], RF_FrontEnd[4B]), RFOUT_FILT (in, see RF_FrontEnd[2D], RF_FrontEnd[4B]), RFOUT_FILT (out, see RF_FrontEnd[2C], RF_FrontEnd[2D])

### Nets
GND: BPF1.2(GND_1) BPF1.3(GND_2) BPF1.5(GND_3) C92.1 C93.2 C94.1 C95.1 C99.2 C100.2 C101.1 C102.2 C105.1 C106.1 IQM1.2(GND_1) IQM1.5(GND_2) IQM1.7(GND_3) IQM1.8(GND_4) IQM1.11(GND_5) IQM1.12(GND_6) IQM1.13(GND_7) IQM1.14(GND_8) IQM1.15(GND_9) IQM1.17(GND_10) IQM1.19(GND_11) IQM1.20(GND_12) IQM1.23(GND_13) IQM1.25(EP) J5.2 J5.3 J5.4 J5.5 J6.2 J7.2 PA1.2(GND) R44.2 R45.2 R46.2 R47.1
MODULATOR_3V3: C92.2 C93.1 C94.2 C95.2 IQM1.18(VCC_1) IQM1.24(VCC_2)
PA_3V3: C100.1 C101.2 C102.1 L12.2
ANT: C104.2 J5.1 ; port ANT
ANT1: C104.1 C106.2 L12.1 PA1.3(RFOUT)
BBI_N: IQM1.22(BBIM) R45.1 ; port BBIN
BBI_P: IQM1.21(BBIP) R44.1 ; port BBIP
BBQ_N: IQM1.9(BBQM) R46.1 ; port BBQN
BBQ_P: IQM1.10(BBQP) R47.2 ; port BBQP
LO1_N: C98.2 IQM1.4(LOM)
LO1_P: C96.2 IQM1.3(LOP)
LO_N: C98.1 ; port LO_N
LO_P: C96.1 ; port LO_P
RFOUT1: C97.1 IQM1.16(RFOUT)
RFOUT_FILT: BPF1.4(OUTPUT_PORT) C103.1 J7.1 ; port RFOUT_FILT
RFOUT_FILT1: C103.2 C105.2 PA1.1(RFIN)
NetBPF1_1: BPF1.1(INPUT_PORT) C97.2 C99.1 J6.1 ; port RFOUT

Not connected (* = marked no-connect by the designer): IQM1 1(PD)* 6(GC)*

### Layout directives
differential pair: BBI_N, BBI_P, BBQ_N, BBQ_P, LO1_N, LO1_P, LO_N, LO_P

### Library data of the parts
BPF1 = CMP-034-000001-3: Signal Conditioning LTCC BAND PASS FLTR 2400-2500MHz; Manufacturer Lifecycle Status: PRODUCTION; Manufacturer_Name: TDK; Impedance: 50Ω; Geometry.Height: 0.6mm; Insertion Loss (dB): 1.25dB; Cutoff Frequency: 2.45GHz
C92 C95 = CMP-2006-01631-1: as C1 on sheet PowerFilterLDO
C93 C94 C102 = CMP-00075-1: as C2 on sheet PowerFilterLDO
C96 C98 C101 C103 = CMP-2006-01799-1: Manufacturer: Vitramon; Part Number: VJ0603A120KXJCW1BC
C97 = CMP-1035-00425-1: CAP 6.8pF 16V ±0.5pF 0603 (1608 Metric) Thickness 1mm SMD; Case-Metric: 1608; Tolerance: Â±0.5pF; Case-EIA: 0603
C99 = CMP-06035-025553-1: Ceramic Capacitor 0.2pF ±0.1pF 250VDC C0G 0603 Paper T/R; Voltage Rating: 250V
C100 = CMP-2006-02556-2: Chip Multilayer Ceramic Capacitors for General Purpose, 0603, 10000pF, C0G, 30ppm/°C, 5%, 50V; Capacitance: 10nF
C104 = CMP-1035-00152-1: CAP 2.2pF 16V ±0.5pF 0603 (1608 Metric) Thickness 1mm SMD; Case-EIA: 0603; Tolerance: Â±0.5pF; Case-Metric: 1608
C105 = CMP-2006-01498-1: Part Number: VJ0603D1R2BXPAJ; Manufacturer: Vitramon
C106 = CMP-2006-00028-1: Manufacturer: Vitramon; Part Number: VJ0603A1R0CXACW1BC
IQM1 = CMP-004-000002-1: TRF3705IRGET, Modulator Quadrature 3.1dB 3.15  3.6 V 24-Pin VQFN; Manufacturer_Name: Texas Instruments; Geometry.Height: 1mm
J5 = CMP-009-000000-1: Description; Manufacturer_Name: Samtec Inc
J6 J7 = CMP-02766-000084-1: as J1 on sheet AnalogBaseband
L12 = CMP-06042-003325-1: Wire Wound Ferrite type RF Inductor 15nH ±5% 2200mA 0.025Ω 0603 (1608); Test Frequency: 10MHz; DC Resistance (DCR): 25mR; Self Resonant Frequency: 2GHz; Current Rating: 2.2A; Shielding: Unshielded
PA1 = CMP-09142-000059-1: IC RF AMP 400MHZ-2.7GHZ SOT89-3; Frequency: 400MHz; Min Supply Voltage: 3.3V; Operating Supply Voltage: 5V; Nominal Supply Current: 104mA; Gain: 13.2dB; Number of Channels: 1; P1dB: 27.4dBm; Max Frequency: 2.7GHz; Max Supply Voltage: 5.5V; Max Power Dissipation: 683mW; Noise Figure: 5.1dB; Operating Frequency: 400 MHz to 2700 MHz; Test Frequency: 2.6GHz
R44-R47 = CMP-00046-1: Res Thin Film 0603 49.9 Ohm 0.1% 1/8W ±25ppm/°C Molded SMD SMD Paper T/R; Power Rating: 125mW; Working Voltage: 75V; Max Power Dissipation: 100mW; Value: 49.9Ω; Voltage Rating (DC): 50V

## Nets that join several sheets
DAC_3V3: PowerFilterLDO (5 pins), AnalogBaseband (11 pins)
FDA_3V3: PowerFilterLDO (5 pins), AnalogBaseband (12 pins)
GND: DSP (8 pins), PowerFilterLDO (63 pins), AnalogBaseband (77 pins), FrequencySynthesis (27 pins), RF_FrontEnd (38 pins)
LPF_3V3: PowerFilterLDO (5 pins), AnalogBaseband (20 pins)
MODULATOR_3V3: PowerFilterLDO (5 pins), RF_FrontEnd (6 pins)
OSC_3V3: PowerFilterLDO (5 pins), FrequencySynthesis (C79.1 C80.1 OSC1.4 R34.1)
PA_3V3: PowerFilterLDO (5 pins), RF_FrontEnd (C100.1 C101.2 C102.1 L12.2)
PICO2_5V: DSP (J9.20), PowerFilterLDO (7 pins)
PLL_3V3: PowerFilterLDO (5 pins), FrequencySynthesis (9 pins)
BBI_N: AnalogBaseband (J3.4 R21.1 U12.15), RF_FrontEnd (IQM1.22 R45.1)
BBI_P: AnalogBaseband (J3.5 R22.1 U13.15), RF_FrontEnd (IQM1.21 R44.1)
BBQ_N: AnalogBaseband (J3.3 R9.1 U10.15), RF_FrontEnd (IQM1.9 R46.1)
BBQ_P: AnalogBaseband (J3.6 R10.1 U11.15), RF_FrontEnd (IQM1.10 R47.2)
LO_N: FrequencySynthesis (C76.2 J4.2), RF_FrontEnd (C98.1)
LO_P: FrequencySynthesis (C73.2 J4.1), RF_FrontEnd (C96.1)
NetJ8_14: DSP (J8.14), FrequencySynthesis (PLL1.1)
NetJ8_15: DSP (J8.15), FrequencySynthesis (PLL1.2)
NetJ8_16: DSP (J8.16), FrequencySynthesis (PLL1.30)
NetJ8_17: DSP (J8.17), FrequencySynthesis (PLL1.4 R38.1)
NetJ8_19: DSP (J8.19), FrequencySynthesis (PLL1.3)
NetJ9_1: DSP (J9.1), AnalogBaseband (U8.6)
NetJ9_2: DSP (J9.2), AnalogBaseband (R4.2 U8.11)
NetJ9_4: DSP (J9.4), AnalogBaseband (R1.1)
NetJ9_5: DSP (J9.5), AnalogBaseband (U8.12)
NetJ9_6: DSP (J9.6), AnalogBaseband (R7.1 U8.13)
NetJ9_7: DSP (J9.7), AnalogBaseband (R8.2 U8.7)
